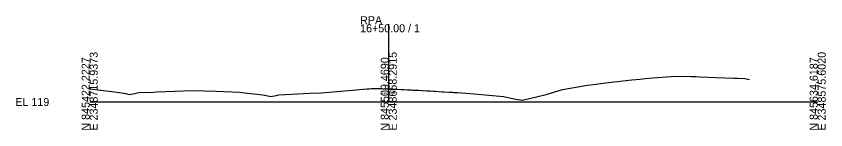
# Model space of a CAD drawing. Extents: x -76 to 2348158, y -10 to 845166.
# Drawn here: x 2759 to 3042.1, y 490.3 to 529.9 of the extents above; entities that cross this region are included whole.
import ezdxf

# ---------------------------------------------------------------- set-up
doc = ezdxf.new("R2010")
doc.units = 0
for name, color, linetype in [('Default', 7, 'Continuous'), ('Exist Cross Section Cell', 7, 'Continuous'), ('Exist XS Center Line Elevation Label', 7, 'Continuous'), ('Exist XS Ground Line', 7, 'Continuous')]:
    doc.layers.add(name, color=color, linetype=linetype)

msp = doc.modelspace()

# ---------------------------------------------------------------- linework, layer by layer
at = {"layer": 'Exist Cross Section Cell'}
for p, q in [((2889.26, 500), (2889.26, 527.12)), ((2784.69, 500), (2889.26, 500)), ((2889.26, 500), (3039.26, 500))]:
    msp.add_line(p, q, dxfattribs=at)
at = {"layer": 'Exist XS Ground Line'}
msp.add_lwpolyline([(2784.69, 504.61), (2792.47, 503.62), (2795.14, 503.3), (2797.18, 502.91), (2798.51, 502.66), (2800.45, 503), (2801.9, 503.27), (2807.04, 503.44), (2808.09, 503.52), (2820.64, 504.01), (2828.95, 503.74), (2837.13, 503.46), (2839.85, 503.06), (2845.25, 502.54), (2846.4, 502.27), (2848.01, 501.89), (2849.91, 502.29), (2850.81, 502.49), (2861.78, 503.02), (2865.69, 503.21), (2876.6, 504.17), (2881.68, 504.61), (2882.41, 504.62), (2883.22, 504.65), (2884.8, 504.7), (2885.24, 504.72), (2886.87, 504.68), (2887.74, 504.64), (2889.26, 504.58), (2889.92, 504.56), (2890.4, 504.54), (2890.71, 504.52), (2892.26, 504.46), (2893.73, 504.39), (2894.5, 504.35), (2895.83, 504.28), (2896.74, 504.23), (2897.22, 504.21), (2897.74, 504.18), (2898.81, 504.12), (2899.7, 504.07), (2900.92, 504), (2902.65, 503.91), (2903.01, 503.89), (2903.58, 503.86), (2904.86, 503.78), (2905.67, 503.73), (2908.1, 503.58), (2908.68, 503.55), (2910.51, 503.47), (2911.05, 503.42), (2911.6, 503.37), (2911.98, 503.34), (2912.98, 503.28), (2913.31, 503.27), (2919.19, 502.83), (2929.43, 501.93), (2933.74, 501.02), (2935.87, 500.59), (2938.49, 501.17), (2944.36, 502.63), (2950.05, 504.3), (2958.77, 505.81), (2960.74, 506.15), (2965.2, 506.66), (2974.24, 507.69), (2977.14, 507.92), (2978.9, 508.22), (2981.63, 508.39), (2989.61, 509.04), (2995.05, 508.89), (2996.82, 508.87), (2998, 508.81), (3003.74, 508.6), (3009.98, 508.32), (3011.26, 508.3), (3013.74, 508.25), (3015.37, 507.85)], dxfattribs=at)

# ---------------------------------------------------------------- texts
at = {"layer": 'Default'}
msp.add_text('-', height=0.0001, dxfattribs=at).set_placement((2784.69, 500))
at = {"layer": 'Exist Cross Section Cell'}
for s, p in [('RPA', (2879.26, 527.12)), ('16+50.00 / 1', (2879.26, 524.32)), ('EL 119', (2758.69, 498.6))]:
    msp.add_text(s, height=2.8, dxfattribs=at).set_placement(p)
for s, p in [('N 845422.2227', (2784.69, 490)), ('E 2348715.9373', (2787.49, 490)), ('N 845509.4690', (2889.26, 490)), ('E 2348658.2915', (2892.06, 490)), ('N 845634.6187', (3039.26, 490)), ('E 2348575.6020', (3042.06, 490))]:
    msp.add_text(s, height=2.8, rotation=90, dxfattribs=at).set_placement(p)
at = {"layer": 'Exist XS Center Line Elevation Label'}
msp.add_text('123.58', height=1.2, dxfattribs=at).set_placement((2886.52, 502.78))

doc.saveas('drawing.dxf')
